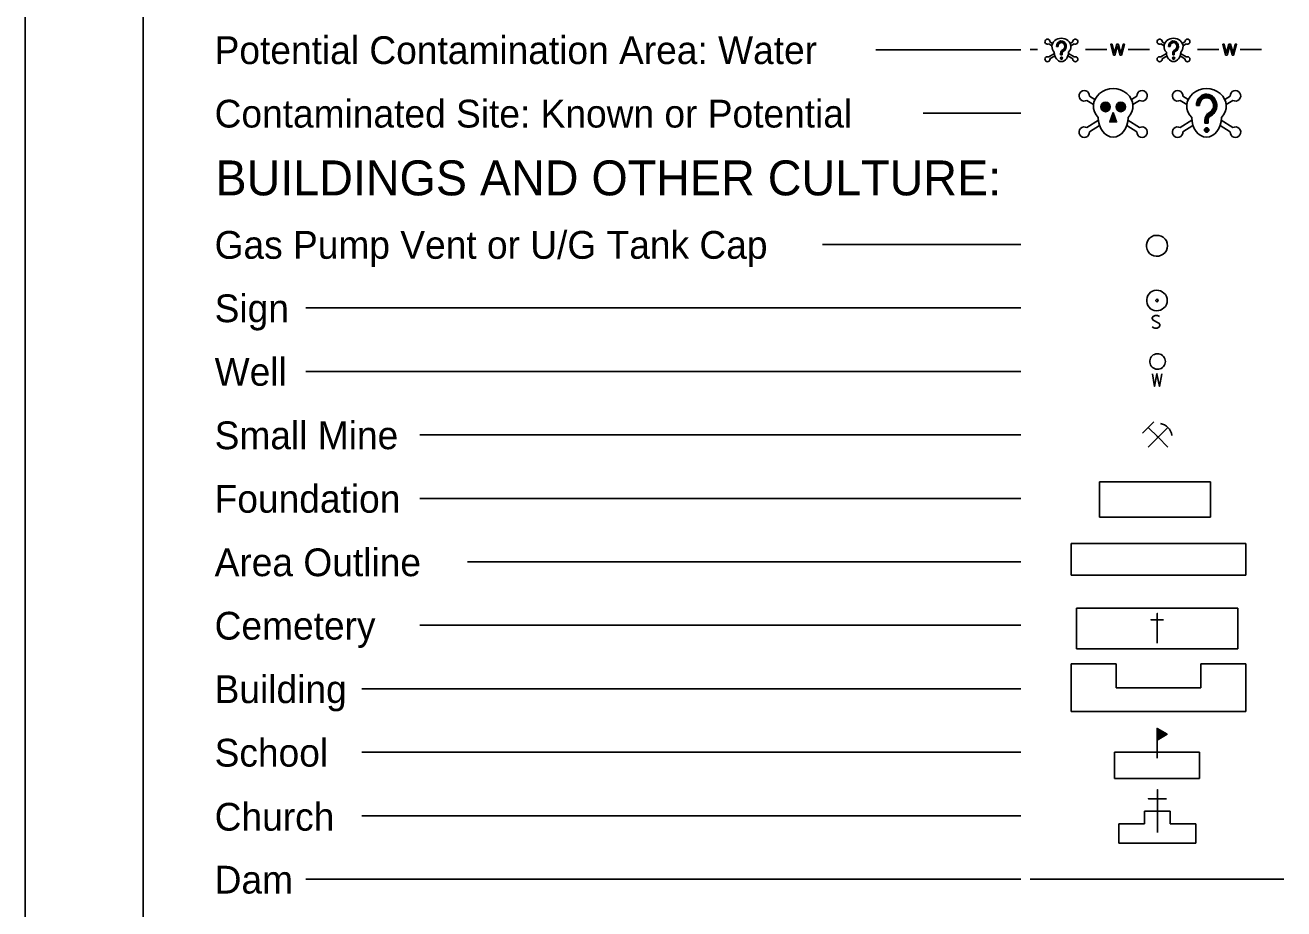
# Model space of a CAD drawing. Extents: x 2040834 to 2047174, y 618431 to 621625.
# Drawn here: x 2045074.4 to 2045541.4, y 620663.6 to 620991.3 of the extents above; entities that cross this region are included whole.
import ezdxf

# ---------------------------------------------------------------- set-up
doc = ezdxf.new("R2010")
doc.units = 0
doc.layers.add('Default', color=7, linetype='Continuous')

msp = doc.modelspace()

# ---------------------------------------------------------------- linework, layer by layer
at = {"layer": 'Default'}
for p, q in [((2045074.38, 621624.54), (2045074.38, 620341.21)), ((2045118.13, 620384.96), (2045118.13, 621580.79)), ((2045454.16, 620984.34), (2045455.35, 620983.6)), ((2045454.63, 620985.09), (2045455.59, 620984.49)), ((2045457.04, 620983.43), (2045457.6, 620983.43)), ((2045463.08, 620985.09), (2045462.12, 620984.49)), ((2045463.55, 620984.34), (2045462.37, 620983.6)), ((2045495.77, 620984.34), (2045496.96, 620983.6)), ((2045496.24, 620985.09), (2045497.2, 620984.49)), ((2045498.65, 620983.43), (2045499.21, 620983.43)), ((2045504.69, 620985.09), (2045503.73, 620984.49)), ((2045505.16, 620984.34), (2045503.98, 620983.6)), ((2045443.84, 620982.19), (2045389.95, 620982.19)), ((2045447.22, 620982.2), (2045449.94, 620982.2)), ((2045456.24, 620980.79), (2045454.16, 620979.49)), ((2045456.44, 620979.87), (2045454.63, 620978.74)), ((2045458.58, 620980.78), (2045458.58, 620980.29)), ((2045458.58, 620980.29), (2045459.14, 620980.29)), ((2045458.66, 620980.78), (2045458.66, 620980.29)), ((2045458.74, 620980.78), (2045458.74, 620980.29)), ((2045458.82, 620980.78), (2045458.82, 620980.29)), ((2045458.86, 620982.2), (2045458.86, 620982.2)), ((2045458.9, 620980.78), (2045458.9, 620980.29)), ((2045458.98, 620980.78), (2045458.98, 620980.29)), ((2045459.06, 620980.78), (2045459.06, 620980.29)), ((2045459.14, 620980.78), (2045459.14, 620980.29)), ((2045461.28, 620979.87), (2045463.08, 620978.74)), ((2045461.48, 620980.79), (2045463.55, 620979.49)), ((2045467.78, 620982.2), (2045475.7, 620982.2)), ((2045483.63, 620982.2), (2045491.55, 620982.2)), ((2045497.85, 620980.79), (2045495.77, 620979.49)), ((2045498.05, 620979.87), (2045496.24, 620978.74)), ((2045500.19, 620980.78), (2045500.19, 620980.29)), ((2045500.19, 620980.29), (2045500.75, 620980.29)), ((2045500.27, 620980.78), (2045500.27, 620980.29)), ((2045500.35, 620980.78), (2045500.35, 620980.29)), ((2045500.43, 620980.78), (2045500.43, 620980.29)), ((2045500.47, 620982.2), (2045500.47, 620982.2)), ((2045500.51, 620980.78), (2045500.51, 620980.29)), ((2045500.59, 620980.78), (2045500.59, 620980.29)), ((2045500.67, 620980.78), (2045500.67, 620980.29)), ((2045500.75, 620980.78), (2045500.75, 620980.29)), ((2045502.89, 620979.87), (2045504.69, 620978.74)), ((2045503.09, 620980.79), (2045505.16, 620979.49)), ((2045509.39, 620982.2), (2045517.31, 620982.2)), ((2045525.24, 620982.2), (2045533.16, 620982.2)), ((2045469.29, 620964.95), (2045471.29, 620963.7)), ((2045486.86, 620964.95), (2045484.86, 620963.7)), ((2045503.93, 620964.95), (2045505.93, 620963.7)), ((2045521.5, 620964.95), (2045519.5, 620963.7)), ((2045468.31, 620963.4), (2045470.78, 620961.85)), ((2045487.83, 620963.4), (2045485.37, 620961.85)), ((2045502.95, 620963.4), (2045505.42, 620961.85)), ((2045508.93, 620961.5), (2045510.1, 620961.5)), ((2045522.47, 620963.4), (2045520.01, 620961.85)), ((2045443.84, 620958.65), (2045407.54, 620958.65)), ((2045472.62, 620956), (2045468.31, 620953.3)), ((2045478.07, 620958.35), (2045478.07, 620958.35)), ((2045483.53, 620956), (2045487.83, 620953.3)), ((2045507.26, 620956), (2045502.95, 620953.3)), ((2045512.13, 620955.99), (2045512.13, 620954.96)), ((2045512.13, 620954.96), (2045513.3, 620954.96)), ((2045512.3, 620955.99), (2045512.3, 620954.96)), ((2045512.46, 620955.99), (2045512.46, 620954.96)), ((2045512.63, 620955.99), (2045512.63, 620954.96)), ((2045512.71, 620958.95), (2045512.71, 620958.95)), ((2045512.8, 620955.99), (2045512.8, 620954.96)), ((2045512.96, 620955.99), (2045512.96, 620954.96)), ((2045513.13, 620955.99), (2045513.13, 620954.96)), ((2045513.3, 620955.99), (2045513.3, 620954.96)), ((2045518.17, 620956), (2045522.47, 620953.3)), ((2045473.03, 620954.1), (2045469.29, 620951.74)), ((2045483.11, 620954.1), (2045486.86, 620951.74)), ((2045507.68, 620954.1), (2045503.93, 620951.74)), ((2045517.75, 620954.1), (2045521.5, 620951.74)), ((2045443.84, 620909.98), (2045370.17, 620909.98)), ((2045443.84, 620886.44), (2045178.49, 620886.44)), ((2045443.84, 620862.9), (2045178.49, 620862.9)), ((2045443.84, 620839.35), (2045220.87, 620839.35)), ((2045491.06, 620842.13), (2045488.93, 620840)), ((2045491.06, 620834.81), (2045498.38, 620842.13)), ((2045494.72, 620838.47), (2045494.31, 620838.88)), ((2045494.72, 620838.47), (2045498.38, 620834.81)), ((2045473.02, 620821.98), (2045514.21, 620821.98)), ((2045473.02, 620808.81), (2045473.02, 620821.98)), ((2045514.21, 620821.98), (2045514.21, 620808.81)), ((2045443.84, 620815.81), (2045220.87, 620815.81)), ((2045514.21, 620808.81), (2045473.02, 620808.81)), ((2045527.25, 620799.1), (2045462.51, 620799.1)), ((2045462.51, 620799.1), (2045462.51, 620787.33)), ((2045527.25, 620787.33), (2045527.25, 620799.1)), ((2045443.84, 620792.27), (2045238.47, 620792.27)), ((2045462.51, 620787.33), (2045527.25, 620787.33)), ((2045464.45, 620775.11), (2045524.32, 620775.11)), ((2045464.45, 620760.05), (2045464.45, 620775.11)), ((2045524.32, 620775.11), (2045524.32, 620760.05)), ((2045443.84, 620768.73), (2045220.87, 620768.73)), ((2045524.32, 620760.05), (2045464.45, 620760.05)), ((2045479.18, 620754.41), (2045462.51, 620754.41)), ((2045462.51, 620754.41), (2045462.51, 620736.76)), ((2045479.18, 620745.58), (2045479.18, 620754.41)), ((2045527.25, 620754.41), (2045510.58, 620754.41)), ((2045510.58, 620754.41), (2045510.58, 620745.58)), ((2045527.25, 620736.76), (2045527.25, 620754.41)), ((2045443.84, 620745.19), (2045199.34, 620745.19)), ((2045510.58, 620745.58), (2045479.18, 620745.58)), ((2045462.51, 620736.76), (2045527.25, 620736.76)), ((2045443.84, 620721.65), (2045199.34, 620721.65)), ((2045478.61, 620721.65), (2045510.06, 620721.65)), ((2045478.61, 620711.88), (2045478.61, 620721.65)), ((2045510.06, 620721.65), (2045510.06, 620711.88)), ((2045510.06, 620711.88), (2045478.61, 620711.88)), ((2045443.84, 620698.1), (2045199.34, 620698.1)), ((2045499.27, 620699.85), (2045489.73, 620699.85)), ((2045489.73, 620699.85), (2045489.73, 620695.1)), ((2045499.27, 620695.1), (2045499.27, 620699.85)), ((2045489.73, 620695.1), (2045480.2, 620695.1)), ((2045480.2, 620695.1), (2045480.2, 620687.94)), ((2045508.8, 620695.1), (2045499.27, 620695.1)), ((2045508.8, 620687.94), (2045508.8, 620695.1)), ((2045480.2, 620687.94), (2045508.8, 620687.94)), ((2045443.84, 620674.56), (2045178.49, 620674.56)), ((2045447.22, 620674.56), (2045541.39, 620674.56))]:
    msp.add_line(p, q, dxfattribs=at)
for points in [[(2045479.58, 620983.24), (2045478.74, 620980.22), (2045478.2, 620980.22), (2045477.15, 620984.18), (2045477.69, 620984.18), (2045478.29, 620981.59)], [(2045478.64, 620981.51), (2045479.39, 620984.18), (2045480.02, 620984.18), (2045480.59, 620982.18)], [(2045481.1, 620981.64), (2045481.72, 620984.18), (2045482.24, 620984.18), (2045481.16, 620980.22), (2045480.65, 620980.22), (2045479.82, 620983.24)], [(2045521.19, 620983.24), (2045520.35, 620980.22), (2045519.81, 620980.22), (2045518.76, 620984.18), (2045519.3, 620984.18), (2045519.9, 620981.59)], [(2045520.25, 620981.51), (2045521, 620984.18), (2045521.63, 620984.18), (2045522.2, 620982.18)], [(2045522.71, 620981.64), (2045523.33, 620984.18), (2045523.85, 620984.18), (2045522.77, 620980.22), (2045522.26, 620980.22), (2045521.43, 620983.24)], [(2045498.26, 620909.48), (2045498.05, 620910.42), (2045497.84, 620911.25), (2045497.32, 620911.98), (2045496.58, 620912.61), (2045495.86, 620913.03), (2045495.02, 620913.34), (2045494.08, 620913.34), (2045493.14, 620913.23), (2045492.31, 620912.82), (2045491.58, 620912.3), (2045491.06, 620911.67), (2045490.64, 620910.83), (2045490.43, 620909.9), (2045490.43, 620909.06), (2045490.64, 620908.13), (2045491.06, 620907.29), (2045491.58, 620906.66), (2045492.31, 620906.14), (2045493.14, 620905.73), (2045494.08, 620905.62), (2045495.02, 620905.62), (2045495.86, 620905.93), (2045496.58, 620906.35), (2045497.32, 620906.98), (2045497.84, 620907.71), (2045498.05, 620908.54), (2045498.26, 620909.48)], [(2045498.15, 620889.17), (2045498.07, 620889.94), (2045497.84, 620890.7), (2045497.46, 620891.39), (2045496.92, 620891.93), (2045496.31, 620892.38), (2045495.62, 620892.77), (2045494.93, 620892.92), (2045494.09, 620892.99), (2045493.33, 620892.84), (2045492.64, 620892.61), (2045491.95, 620892.23), (2045491.41, 620891.7), (2045490.96, 620891.01), (2045490.65, 620890.32), (2045490.5, 620889.55), (2045490.5, 620888.79), (2045490.65, 620888.03), (2045490.96, 620887.34), (2045491.41, 620886.65), (2045491.95, 620886.11), (2045492.64, 620885.73), (2045493.33, 620885.5), (2045494.09, 620885.35), (2045494.93, 620885.42), (2045495.62, 620885.58), (2045496.31, 620885.96), (2045496.92, 620886.42), (2045497.46, 620886.96), (2045497.84, 620887.64), (2045498.07, 620888.41), (2045498.15, 620889.17)], [(2045494.48, 620889.63), (2045494.25, 620889.63), (2045494.02, 620889.48), (2045493.86, 620889.25), (2045493.94, 620889.02), (2045494.09, 620888.79), (2045494.32, 620888.71), (2045494.55, 620888.79), (2045494.7, 620888.94), (2045494.78, 620889.25), (2045494.7, 620889.48), (2045494.48, 620889.63)], [(2045495.22, 620883.28), (2045494.48, 620883.61), (2045493.62, 620883.61), (2045492.85, 620883.28), (2045492.51, 620882.69), (2045492.51, 620882.46), (2045492.88, 620881.91), (2045495.03, 620880.8), (2045495.4, 620880.28), (2045495.37, 620879.83), (2045495.03, 620879.24), (2045494.4, 620878.9), (2045493.51, 620878.9), (2045493.1, 620879.05), (2045492.51, 620879.46)], [(2045497.44, 620866.56), (2045497.35, 620867.07), (2045497.25, 620867.58), (2045497.02, 620868.04), (2045496.7, 620868.45), (2045496.33, 620868.83), (2045495.91, 620869.11), (2045495.4, 620869.29), (2045494.89, 620869.43), (2045494.38, 620869.43), (2045493.87, 620869.38), (2045493.36, 620869.2), (2045492.94, 620868.97), (2045492.53, 620868.64), (2045492.16, 620868.27), (2045491.92, 620867.81), (2045491.74, 620867.34), (2045491.65, 620866.83), (2045491.65, 620866.28), (2045491.74, 620865.77), (2045491.92, 620865.3), (2045492.16, 620864.84), (2045492.53, 620864.47), (2045492.94, 620864.15), (2045493.36, 620863.91), (2045493.87, 620863.73), (2045494.38, 620863.68), (2045494.89, 620863.68), (2045495.4, 620863.82), (2045495.91, 620864.01), (2045496.33, 620864.28), (2045496.7, 620864.66), (2045497.02, 620865.07), (2045497.25, 620865.54), (2045497.35, 620866.05), (2045497.44, 620866.56)], [(2045492.63, 620862.01), (2045493.37, 620857.31), (2045494.33, 620862.01), (2045495.3, 620857.31), (2045496.11, 620862.01)], [(2045494.72, 620838.47), (2045491.06, 620842.13), (2045493.12, 620844.2)], [(2045499.86, 620839.12), (2045499.68, 620839.95), (2045499.39, 620840.71), (2045498.97, 620841.42), (2045498.44, 620842.01), (2045497.85, 620842.6), (2045497.14, 620843.02), (2045496.37, 620843.37), (2045495.61, 620843.55)], [(2045494.41, 620762.08), (2045494.41, 620773.11), (2045494.41, 620770.77), (2045492.06, 620770.77), (2045496.76, 620770.77)], [(2045494.38, 620719.45), (2045494.38, 620730.49), (2045498.07, 620728.32), (2045494.38, 620726.14), (2045494.6, 620726.49), (2045494.6, 620730.18), (2045497.64, 620728.27), (2045494.82, 620726.62), (2045494.86, 620729.84), (2045497.29, 620728.27), (2045495.08, 620727.01), (2045495.08, 620729.45), (2045496.9, 620728.27), (2045495.34, 620727.4), (2045495.34, 620729.05), (2045496.51, 620728.32), (2045495.55, 620727.75), (2045495.55, 620728.66), (2045496.16, 620728.32), (2045495.77, 620728.1), (2045495.73, 620728.36), (2045495.86, 620728.32)], [(2045494.5, 620691.91), (2045494.5, 620707.8), (2045494.5, 620704.42), (2045491.12, 620704.42), (2045497.88, 620704.42)]]:
    msp.add_lwpolyline(points, dxfattribs=at)
for points in [[(2045478.07, 620958.95), (2045476.78, 620955.42), (2045479.36, 620955.42)], [(2045478.07, 620958.35), (2045477.08, 620955.63), (2045479.07, 620955.63)], [(2045478.07, 620957.75), (2045477.37, 620955.83), (2045478.77, 620955.83)], [(2045478.07, 620957.15), (2045477.67, 620956.04), (2045478.48, 620956.04)], [(2045478.07, 620956.55), (2045477.96, 620956.24), (2045478.18, 620956.24)]]:
    msp.add_lwpolyline(points, close=True, dxfattribs=at)
for centre, radius in [((2045458.88, 620979.07), 0.401), ((2045458.88, 620979.07), 0.312), ((2045458.88, 620979.07), 0.221), ((2045458.88, 620979.07), 0.132), ((2045458.88, 620979.07), 0.0428), ((2045500.49, 620979.07), 0.401), ((2045500.49, 620979.07), 0.312), ((2045500.49, 620979.07), 0.221), ((2045500.49, 620979.07), 0.132), ((2045500.49, 620979.07), 0.0428), ((2045475.23, 620960.95), 1.75), ((2045475.23, 620960.95), 1.54), ((2045475.23, 620960.95), 1.33), ((2045475.23, 620960.95), 1.13), ((2045475.23, 620960.95), 0.923), ((2045475.23, 620960.95), 0.717), ((2045475.23, 620960.95), 0.511), ((2045475.23, 620960.95), 0.305), ((2045475.23, 620960.95), 0.0988), ((2045480.91, 620960.95), 1.75), ((2045480.91, 620960.95), 1.54), ((2045480.91, 620960.95), 1.33), ((2045480.91, 620960.95), 1.13), ((2045480.91, 620960.95), 0.923), ((2045480.91, 620960.95), 0.717), ((2045480.91, 620960.95), 0.511), ((2045480.91, 620960.95), 0.305), ((2045480.91, 620960.95), 0.0988), ((2045512.75, 620952.43), 0.834), ((2045512.75, 620952.43), 0.649), ((2045512.75, 620952.43), 0.46), ((2045512.75, 620952.43), 0.274), ((2045512.75, 620952.43), 0.0889)]:
    msp.add_circle(centre, radius, dxfattribs=at)
for centre, radius, start, end in [((2045453.7, 620985.16), 0.939, 355.8976, 299.8062), ((2045464.02, 620985.16), 0.939, 240.1938, 184.1024), ((2045495.31, 620985.16), 0.939, 355.8976, 299.8062), ((2045505.63, 620985.16), 0.939, 240.1938, 184.1024), ((2045453.7, 620978.67), 0.939, 60.1938, 4.1024), ((2045464.02, 620978.67), 0.939, 175.8976, 119.8062), ((2045495.31, 620978.67), 0.939, 60.1938, 4.1024), ((2045505.63, 620978.67), 0.939, 175.8976, 119.8062), ((2045467.34, 620965.09), 1.95, 355.8976, 299.8062), ((2045488.8, 620965.09), 1.95, 240.1938, 184.1024), ((2045501.98, 620965.09), 1.95, 355.8976, 299.8062), ((2045523.44, 620965.09), 1.95, 240.1938, 184.1024), ((2045467.34, 620951.6), 1.95, 60.1938, 4.1024), ((2045488.8, 620951.6), 1.95, 175.8976, 119.8062), ((2045501.98, 620951.6), 1.95, 60.1938, 4.1024), ((2045523.44, 620951.6), 1.95, 175.8976, 119.8062)]:
    msp.add_arc(centre, radius, start, end, dxfattribs=at)
for centre, major_axis, ratio, start_param, end_param in [((2045458.86, 620983.32), (3.52, 0), 0.885014, 5.564242, 10.143721), ((2045458.86, 620983.43), (0, 2.02), 0.9, 3.567618, 7.853982), ((2045458.86, 620983.43), (0, 1.93), 0.9, 3.567618, 7.853982), ((2045458.86, 620983.43), (0, 1.84), 0.9, 3.567618, 7.853982), ((2045458.86, 620983.43), (0, 1.75), 0.9, 3.567618, 7.853982), ((2045458.86, 620983.43), (0, 1.66), 0.9, 3.567618, 7.853982), ((2045458.86, 620983.43), (0, 1.58), 0.9, 3.567618, 7.853982), ((2045458.86, 620983.43), (0, 1.49), 0.9, 3.567618, 7.853982), ((2045458.86, 620983.43), (0, 1.4), 0.9, 3.567618, 7.853982), ((2045500.47, 620983.32), (3.52, 0), 0.885014, 5.564242, 10.143721), ((2045500.47, 620983.43), (0, 2.02), 0.9, 3.567618, 7.853982), ((2045500.47, 620983.43), (0, 1.93), 0.9, 3.567618, 7.853982), ((2045500.47, 620983.43), (0, 1.84), 0.9, 3.567618, 7.853982), ((2045500.47, 620983.43), (0, 1.75), 0.9, 3.567618, 7.853982), ((2045500.47, 620983.43), (0, 1.66), 0.9, 3.567618, 7.853982), ((2045500.47, 620983.43), (0, 1.58), 0.9, 3.567618, 7.853982), ((2045500.47, 620983.43), (0, 1.49), 0.9, 3.567618, 7.853982), ((2045500.47, 620983.43), (0, 1.4), 0.9, 3.567618, 7.853982), ((2045458.86, 620981.3), (0, -3.52), 0.752542, 4.722735, 7.843636), ((2045459.94, 620980.78), (0, 1.52), 0.9, 0.426026, 1.570796), ((2045459.94, 620980.78), (0, 1.43), 0.9, 0.426026, 1.570796), ((2045459.94, 620980.78), (0, 1.34), 0.9, 0.426026, 1.570796), ((2045459.94, 620980.78), (0, 1.25), 0.9, 0.426026, 1.570796), ((2045459.94, 620980.78), (0, 1.16), 0.9, 0.426026, 1.570796), ((2045459.94, 620980.78), (0, 1.07), 0.9, 0.426026, 1.570796), ((2045459.94, 620980.78), (0, 0.981), 0.9, 0.426026, 1.570796), ((2045459.94, 620980.78), (0, 0.892), 0.9, 0.426026, 1.570796), ((2045500.47, 620981.3), (0, -3.52), 0.752542, 4.722735, 7.843636), ((2045501.55, 620980.78), (0, 1.52), 0.9, 0.426026, 1.570796), ((2045501.55, 620980.78), (0, 1.43), 0.9, 0.426026, 1.570796), ((2045501.55, 620980.78), (0, 1.34), 0.9, 0.426026, 1.570796), ((2045501.55, 620980.78), (0, 1.25), 0.9, 0.426026, 1.570796), ((2045501.55, 620980.78), (0, 1.16), 0.9, 0.426026, 1.570796), ((2045501.55, 620980.78), (0, 1.07), 0.9, 0.426026, 1.570796), ((2045501.55, 620980.78), (0, 0.981), 0.9, 0.426026, 1.570796), ((2045501.55, 620980.78), (0, 0.892), 0.9, 0.426026, 1.570796), ((2045478.07, 620961.26), (7.32, 0), 0.885014, 5.564242, 10.143721), ((2045512.71, 620961.26), (7.32, 0), 0.885014, 5.564242, 10.143721), ((2045512.71, 620961.5), (0, 4.2), 0.9, 3.567618, 7.853982), ((2045512.71, 620961.5), (0, 4.02), 0.9, 3.567618, 7.853982), ((2045512.71, 620961.5), (0, 3.83), 0.9, 3.567618, 7.853982), ((2045512.71, 620961.5), (0, 3.65), 0.9, 3.567618, 7.853982), ((2045512.71, 620961.5), (0, 3.46), 0.9, 3.567618, 7.853982), ((2045512.71, 620961.5), (0, 3.28), 0.9, 3.567618, 7.853982), ((2045512.71, 620961.5), (0, 3.09), 0.9, 3.567618, 7.853982), ((2045512.71, 620961.5), (0, 2.9), 0.9, 3.567618, 7.853982), ((2045478.07, 620957.07), (0, -7.32), 0.752542, 4.722735, 7.843636), ((2045512.71, 620957.07), (0, -7.32), 0.752542, 4.722735, 7.843636), ((2045514.97, 620955.99), (0, 3.15), 0.9, 0.426026, 1.570796), ((2045514.97, 620955.99), (0, 2.97), 0.9, 0.426026, 1.570796), ((2045514.97, 620955.99), (0, 2.78), 0.9, 0.426026, 1.570796), ((2045514.97, 620955.99), (0, 2.6), 0.9, 0.426026, 1.570796), ((2045514.97, 620955.99), (0, 2.41), 0.9, 0.426026, 1.570796), ((2045514.97, 620955.99), (0, 2.22), 0.9, 0.426026, 1.570796), ((2045514.97, 620955.99), (0, 2.04), 0.9, 0.426026, 1.570796), ((2045514.97, 620955.99), (0, 1.85), 0.9, 0.426026, 1.570796)]:
    msp.add_ellipse(centre, major_axis=major_axis, ratio=ratio, start_param=start_param, end_param=end_param, dxfattribs=at)
for points in [[(2045479.69, 620983.71), (2045479.63, 620983.43), (2045479.58, 620983.24)], [(2045479.82, 620983.24), (2045479.71, 620983.62), (2045479.69, 620983.71)], [(2045521.3, 620983.71), (2045521.24, 620983.43), (2045521.19, 620983.24)], [(2045521.43, 620983.24), (2045521.32, 620983.62), (2045521.3, 620983.71)], [(2045478.29, 620981.59), (2045478.39, 620981.18), (2045478.46, 620980.78)], [(2045478.46, 620980.78), (2045478.61, 620981.41), (2045478.64, 620981.51)], [(2045480.59, 620982.18), (2045480.8, 620981.43), (2045480.9, 620980.78)], [(2045480.9, 620980.78), (2045480.98, 620981.15), (2045481.1, 620981.64)], [(2045519.9, 620981.59), (2045520, 620981.18), (2045520.07, 620980.78)], [(2045520.07, 620980.78), (2045520.22, 620981.41), (2045520.25, 620981.51)], [(2045522.2, 620982.18), (2045522.41, 620981.43), (2045522.51, 620980.78)], [(2045522.51, 620980.78), (2045522.59, 620981.15), (2045522.71, 620981.64)]]:
    msp.add_open_spline(points, degree=2, dxfattribs=at)

# ---------------------------------------------------------------- texts
for s, height, p in [('Potential Contamination Area: Water', 10.2996, (2045144.67, 620976.86)), ('Contaminated Site: Known or Potential', 10.2996, (2045144.67, 620953.32)), ('BUILDINGS AND OTHER CULTURE:', 12.9481, (2045144.99, 620928.17)), ('Gas Pump Vent or U/G Tank Cap', 10.2996, (2045144.67, 620904.65)), ('Sign', 10.3, (2045144.68, 620881.13)), ('Well', 10.3, (2045144.68, 620857.58)), ('Small Mine', 10.3, (2045144.68, 620834.03)), ('Foundation', 10.3, (2045144.68, 620810.49)), ('Area Outline', 10.2996, (2045144.68, 620786.94)), ('Cemetery', 10.3, (2045144.67, 620763.42)), ('Building', 10.3, (2045144.68, 620739.88)), ('School', 10.3, (2045144.67, 620716.33)), ('Church', 10.3, (2045144.69, 620692.57)), ('Dam', 10.3, (2045144.68, 620669.25))]:
    msp.add_text(s, height=height, dxfattribs=at).set_placement(p)

doc.saveas('drawing.dxf')
